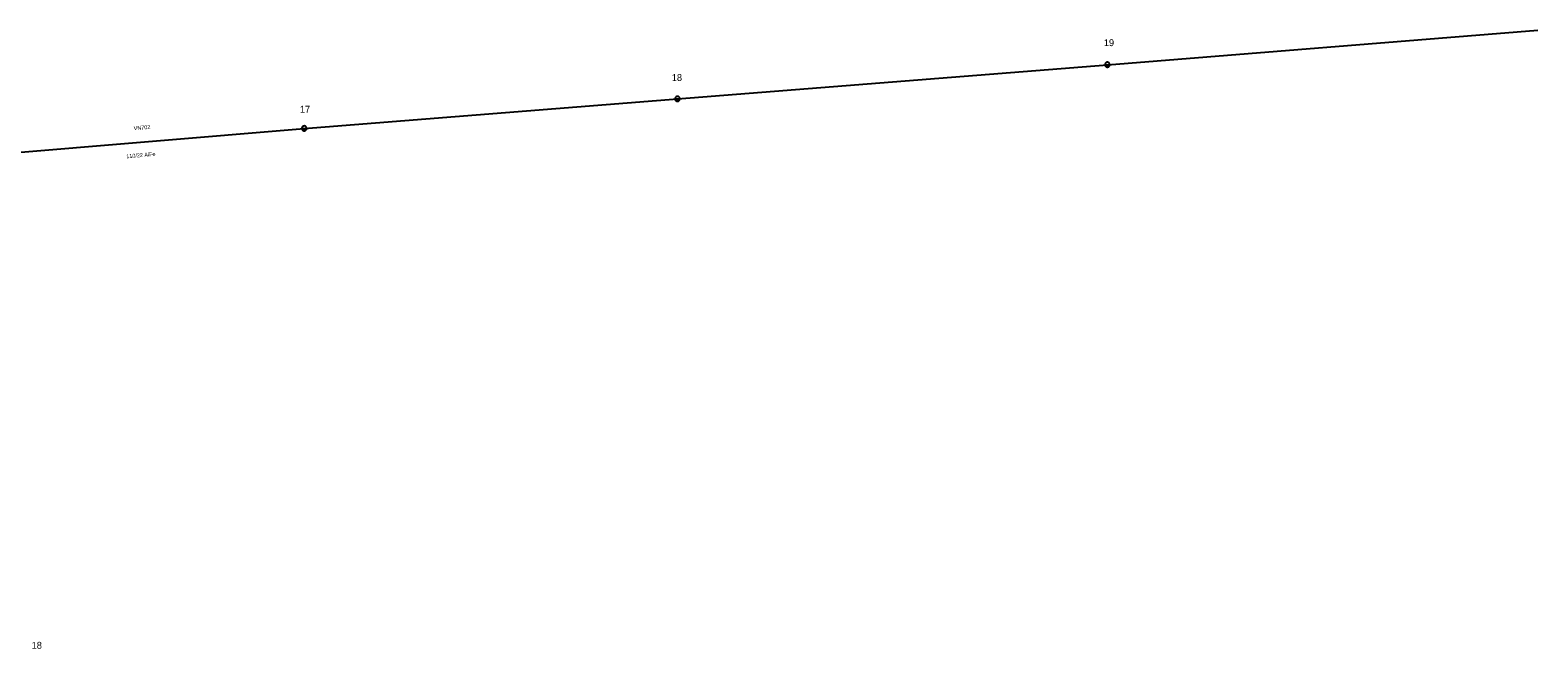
# Model space of a CAD drawing. Extents: x -545588 to -543214, y -1196037 to -1194452.
# Drawn here: x -543597.4 to -543214, y -1195997.2 to -1195839.9 of the extents above; entities that cross this region are included whole.
import ezdxf

# ---------------------------------------------------------------- set-up
doc = ezdxf.new("R2010")
doc.units = 0
for name, color, linetype in [('Vrstva 1', 7, 'Continuous'), ('Vrstva 13', 7, 'Continuous'), ('Vrstva 14', 7, 'Continuous'), ('Vrstva 2', 7, 'Continuous'), ('Vrstva 3', 7, 'Continuous')]:
    doc.layers.add(name, color=color, linetype=linetype)

# ---------------------------------------------------------------- blocks, each defined once
blk = doc.blocks.new('VN440')
at = {"layer": 'Vrstva 2'}
for points in [[(1.22, 0), (1.21, 0.13), (1.19, 0.25), (1.16, 0.38), (1.11, 0.5), (1.05, 0.61), (0.98, 0.72), (0.9, 0.82), (0.81, 0.91), (0.71, 0.99), (0.6, 1.06), (0.49, 1.12), (0.37, 1.16), (0.25, 1.2), (0.12, 1.22), (-0.01, 1.22), (-0.14, 1.22), (-0.26, 1.2), (-0.39, 1.16), (-0.51, 1.12), (-0.62, 1.06), (-0.73, 0.99), (-0.83, 0.91), (-0.92, 0.82), (-1, 0.72), (-1.07, 0.61), (-1.13, 0.5), (-1.18, 0.38), (-1.21, 0.25), (-1.23, 0.13), (-1.24, 0), (-1.23, -0.13), (-1.21, -0.26), (-1.18, -0.38), (-1.13, -0.5), (-1.07, -0.62), (-1, -0.73), (-0.92, -0.83), (-0.83, -0.92), (-0.73, -1), (-0.62, -1.07), (-0.51, -1.13), (-0.39, -1.17), (-0.26, -1.2), (-0.14, -1.23), (-0.01, -1.23), (0.12, -1.23), (0.25, -1.2), (0.37, -1.17), (0.49, -1.13), (0.6, -1.07), (0.71, -1), (0.81, -0.92), (0.9, -0.83), (0.98, -0.73), (1.05, -0.62), (1.11, -0.5), (1.16, -0.38), (1.19, -0.26), (1.21, -0.13), (1.22, 0)], [(-1.24, 0), (1.22, 0)], [(-1.18, -0.34), (1.1, -0.34)], [(-1.01, -0.63), (0.97, -0.63)], [(-0.74, -0.92), (0.68, -0.92)]]:
    blk.add_lwpolyline(points, dxfattribs=at)

msp = doc.modelspace()

# ---------------------------------------------------------------- linework, layer by layer
at = {"layer": 'Vrstva 1'}
msp.add_lwpolyline([(-543605.91, -1195871.36), (-543527.67, -1195864.84), (-543432.77, -1195857.32), (-543323.46, -1195848.64), (-543214.01, -1195839.86)], dxfattribs=at)

# ---------------------------------------------------------------- block references
at = {"layer": 'Vrstva 13'}
for p, xscale, yscale, rotation in [((-543323.46, -1195848.64), 0.49999999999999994, 0.5000000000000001, 4.544069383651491), ((-543432.77, -1195857.32), 0.5, 0.5, 4.530130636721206), ((-543527.67, -1195864.84), 0.5, 0.5, 4.762719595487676)]:
    msp.add_blockref('VN440', p, dxfattribs=dict(at, xscale=xscale, yscale=yscale, rotation=rotation))

# ---------------------------------------------------------------- texts
at = {"layer": 'Vrstva 14'}
for s, p in [('19', (-543324.36, -1195843.92)), ('18', (-543434.21, -1195852.78)), ('17', (-543528.77, -1195860.85)), ('18', (-543596.98, -1195997.2))]:
    msp.add_text(s, height=1.75, dxfattribs=at).set_placement(p)
at = {"layer": 'Vrstva 2'}
msp.add_text('110/22 AlFe', height=1, rotation=4.763, dxfattribs=at).set_placement((-543572.87, -1195872.46))
at = {"layer": 'Vrstva 3'}
msp.add_text('VN702', height=1, rotation=4.763, dxfattribs=at).set_placement((-543570.98, -1195865.32))

doc.saveas('drawing.dxf')
